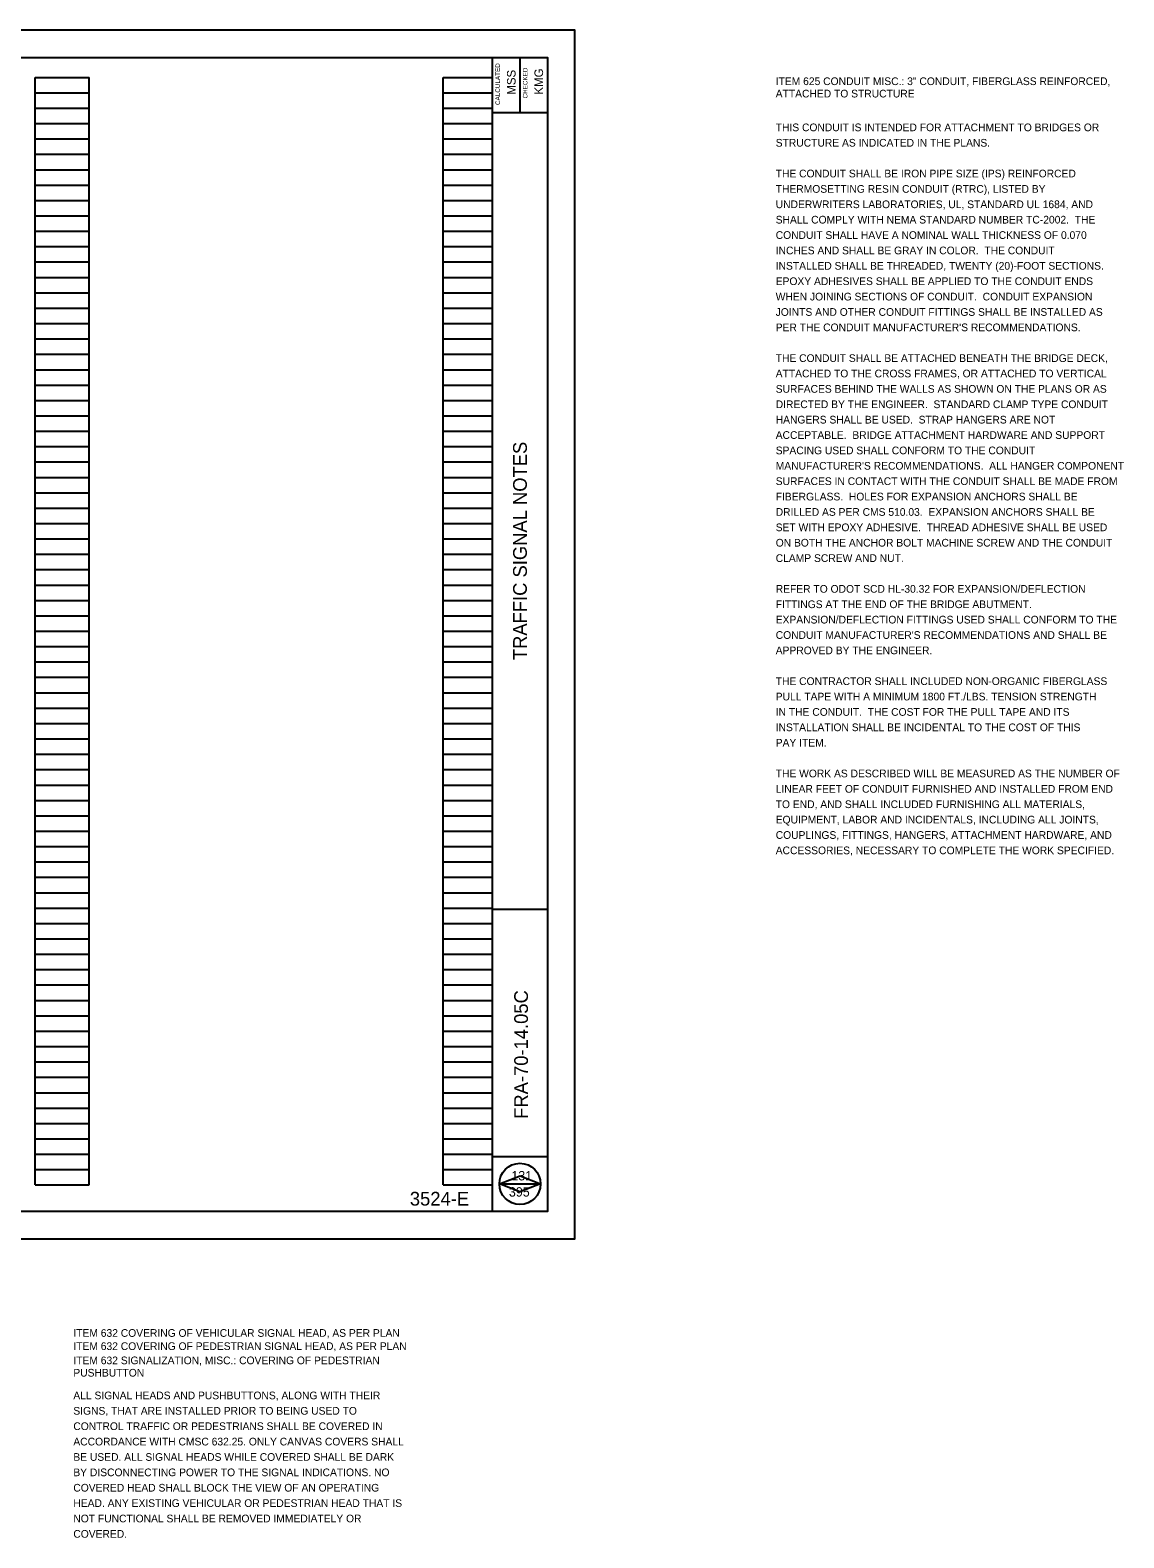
# Model space of a CAD drawing. Extents: x -50.5 to 43.5, y -13 to 19.8.
# Drawn here: x 23.58 to 43.48, y -12.95 to 14.49 of the extents above; entities that cross this region are included whole.
import ezdxf

# ---------------------------------------------------------------- set-up
doc = ezdxf.new("R2010")
doc.units = 0
for name, color, linetype in [('Level 63', 7, 'Continuous'), ('PF_P_Text', 7, 'Continuous'), ('SC_Scratch1', 7, 'Continuous'), ('SH_Cut_Line', 7, 'Continuous'), ('SH_Data', 7, 'Continuous'), ('SH_Text', 7, 'Continuous')]:
    doc.layers.add(name, color=color, linetype=linetype)

msp = doc.modelspace()

# ---------------------------------------------------------------- linework, layer by layer
at = {"layer": 'Level 63'}
msp.add_line((32.119, -6.508), (32.869, -6.508), dxfattribs=at)
msp.add_circle((32.494, -6.508), 0.375, dxfattribs=at)
at = {"layer": 'PF_P_Text'}
for p, q in [((31.994, -7.008), (31.994, 13.992)), ((32.494, 13.992), (32.494, 12.992)), ((31.994, 12.992), (32.994, 12.992)), ((31.994, -1.508), (32.994, -1.508)), ((31.994, -6.008), (32.994, -6.008))]:
    msp.add_line(p, q, dxfattribs=at)
msp.add_lwpolyline([(1.494, 13.992), (32.994, 13.992), (32.994, -7.008), (1.494, -7.008)], close=True, dxfattribs=at)
at = {"layer": 'SC_Scratch1'}
for p, q in [((23.674, -6.528), (23.674, 13.632)), ((23.674, 13.632), (24.654, 13.632)), ((24.654, -6.528), (24.654, 13.632)), ((31.094, -6.528), (31.094, 13.632)), ((31.094, 13.632), (31.994, 13.632)), ((31.994, -6.528), (31.994, 13.632)), ((23.674, 13.352), (24.654, 13.352)), ((31.094, 13.352), (31.994, 13.352)), ((23.674, 13.072), (24.654, 13.072)), ((31.094, 13.072), (31.994, 13.072)), ((23.674, 12.792), (24.654, 12.792)), ((31.094, 12.792), (31.994, 12.792)), ((23.674, 12.512), (24.654, 12.512)), ((31.094, 12.512), (31.994, 12.512)), ((23.674, 12.232), (24.654, 12.232)), ((31.094, 12.232), (31.994, 12.232)), ((23.674, 11.952), (24.654, 11.952)), ((31.094, 11.952), (31.994, 11.952)), ((23.674, 11.672), (24.654, 11.672)), ((31.094, 11.672), (31.994, 11.672)), ((23.674, 11.392), (24.654, 11.392)), ((31.094, 11.392), (31.994, 11.392)), ((23.674, 11.112), (24.654, 11.112)), ((31.094, 11.112), (31.994, 11.112)), ((23.674, 10.832), (24.654, 10.832)), ((31.094, 10.832), (31.994, 10.832)), ((23.674, 10.552), (24.654, 10.552)), ((31.094, 10.552), (31.994, 10.552)), ((23.674, 10.272), (24.654, 10.272)), ((31.094, 10.272), (31.994, 10.272)), ((23.674, 9.992), (24.654, 9.992)), ((31.094, 9.992), (31.994, 9.992)), ((23.674, 9.712), (24.654, 9.712)), ((31.094, 9.712), (31.994, 9.712)), ((23.674, 9.432), (24.654, 9.432)), ((31.094, 9.432), (31.994, 9.432)), ((23.674, 9.152), (24.654, 9.152)), ((31.094, 9.152), (31.994, 9.152)), ((23.674, 8.872), (24.654, 8.872)), ((31.094, 8.872), (31.994, 8.872)), ((23.674, 8.592), (24.654, 8.592)), ((31.094, 8.592), (31.994, 8.592)), ((23.674, 8.312), (24.654, 8.312)), ((31.094, 8.312), (31.994, 8.312)), ((23.674, 8.032), (24.654, 8.032)), ((31.094, 8.032), (31.994, 8.032)), ((23.674, 7.752), (24.654, 7.752)), ((31.094, 7.752), (31.994, 7.752)), ((23.674, 7.472), (24.654, 7.472)), ((31.094, 7.472), (31.994, 7.472)), ((23.674, 7.192), (24.654, 7.192)), ((31.094, 7.192), (31.994, 7.192)), ((23.674, 6.912), (24.654, 6.912)), ((31.094, 6.912), (31.994, 6.912)), ((23.674, 6.632), (24.654, 6.632)), ((31.094, 6.632), (31.994, 6.632)), ((23.674, 6.352), (24.654, 6.352)), ((31.094, 6.352), (31.994, 6.352)), ((23.674, 6.072), (24.654, 6.072)), ((31.094, 6.072), (31.994, 6.072)), ((23.674, 5.792), (24.654, 5.792)), ((31.094, 5.792), (31.994, 5.792)), ((23.674, 5.512), (24.654, 5.512)), ((31.094, 5.512), (31.994, 5.512)), ((23.674, 5.232), (24.654, 5.232)), ((31.094, 5.232), (31.994, 5.232)), ((23.674, 4.952), (24.654, 4.952)), ((31.094, 4.952), (31.994, 4.952)), ((23.674, 4.672), (24.654, 4.672)), ((31.094, 4.672), (31.994, 4.672)), ((23.674, 4.392), (24.654, 4.392)), ((31.094, 4.392), (31.994, 4.392)), ((23.674, 4.112), (24.654, 4.112)), ((31.094, 4.112), (31.994, 4.112)), ((23.674, 3.832), (24.654, 3.832)), ((31.094, 3.832), (31.994, 3.832)), ((23.674, 3.552), (24.654, 3.552)), ((31.094, 3.552), (31.994, 3.552)), ((23.674, 3.272), (24.654, 3.272)), ((31.094, 3.272), (31.994, 3.272)), ((23.674, 2.992), (24.654, 2.992)), ((31.094, 2.992), (31.994, 2.992)), ((23.674, 2.712), (24.654, 2.712)), ((31.094, 2.712), (31.994, 2.712)), ((23.674, 2.432), (24.654, 2.432)), ((31.094, 2.432), (31.994, 2.432)), ((23.674, 2.152), (24.654, 2.152)), ((31.094, 2.152), (31.994, 2.152)), ((23.674, 1.872), (24.654, 1.872)), ((31.094, 1.872), (31.994, 1.872)), ((23.674, 1.592), (24.654, 1.592)), ((31.094, 1.592), (31.994, 1.592)), ((23.674, 1.312), (24.654, 1.312)), ((31.094, 1.312), (31.994, 1.312)), ((23.674, 1.032), (24.654, 1.032)), ((31.094, 1.032), (31.994, 1.032)), ((23.674, 0.752), (24.654, 0.752)), ((31.094, 0.752), (31.994, 0.752)), ((23.674, 0.472), (24.654, 0.472)), ((31.094, 0.472), (31.994, 0.472)), ((23.674, 0.192), (24.654, 0.192)), ((31.094, 0.192), (31.994, 0.192)), ((23.674, -0.088), (24.654, -0.088)), ((31.094, -0.088), (31.994, -0.088)), ((23.674, -0.368), (24.654, -0.368)), ((31.094, -0.368), (31.994, -0.368)), ((23.674, -0.648), (24.654, -0.648)), ((31.094, -0.648), (31.994, -0.648)), ((23.674, -0.928), (24.654, -0.928)), ((31.094, -0.928), (31.994, -0.928)), ((23.674, -1.208), (24.654, -1.208)), ((31.094, -1.208), (31.994, -1.208)), ((23.674, -1.488), (24.654, -1.488)), ((31.094, -1.488), (31.994, -1.488)), ((23.674, -1.768), (24.654, -1.768)), ((31.094, -1.768), (31.994, -1.768)), ((23.674, -2.048), (24.654, -2.048)), ((31.094, -2.048), (31.994, -2.048)), ((23.674, -2.328), (24.654, -2.328)), ((31.094, -2.328), (31.994, -2.328)), ((23.674, -2.608), (24.654, -2.608)), ((31.094, -2.608), (31.994, -2.608)), ((23.674, -2.888), (24.654, -2.888)), ((31.094, -2.888), (31.994, -2.888)), ((23.674, -3.168), (24.654, -3.168)), ((31.094, -3.168), (31.994, -3.168)), ((23.674, -3.448), (24.654, -3.448)), ((31.094, -3.448), (31.994, -3.448)), ((23.674, -3.728), (24.654, -3.728)), ((31.094, -3.728), (31.994, -3.728)), ((23.674, -4.008), (24.654, -4.008)), ((31.094, -4.008), (31.994, -4.008)), ((23.674, -4.288), (24.654, -4.288)), ((31.094, -4.288), (31.994, -4.288)), ((23.674, -4.568), (24.654, -4.568)), ((31.094, -4.568), (31.994, -4.568)), ((23.674, -4.848), (24.654, -4.848)), ((31.094, -4.848), (31.994, -4.848)), ((23.674, -5.128), (24.654, -5.128)), ((31.094, -5.128), (31.994, -5.128)), ((23.674, -5.408), (24.654, -5.408)), ((31.094, -5.408), (31.994, -5.408)), ((23.674, -5.688), (24.654, -5.688)), ((31.094, -5.688), (31.994, -5.688)), ((23.674, -5.968), (24.654, -5.968)), ((31.094, -5.968), (31.994, -5.968)), ((23.674, -6.248), (24.654, -6.248)), ((31.094, -6.248), (31.994, -6.248)), ((23.674, -6.528), (24.654, -6.528)), ((31.094, -6.528), (31.994, -6.528)), ((32.119, -6.508), (32.495, -6.36)), ((32.49, -6.654), (32.119, -6.508)), ((32.869, -6.508), (32.49, -6.654)), ((32.495, -6.36), (32.869, -6.508))]:
    msp.add_line(p, q, dxfattribs=at)
at = {"layer": 'SH_Cut_Line'}
msp.add_lwpolyline([(-0.506, -7.508), (33.494, -7.508), (33.494, 14.492), (-0.506, 14.492)], close=True, dxfattribs=at)

# ---------------------------------------------------------------- texts
at = {"layer": 'Level 63'}
for s, p in [('CALCULATED', (32.13, 13.129)), ('CHECKED', (32.63, 13.248))]:
    msp.add_text(s, height=0.0833, rotation=90, dxfattribs=at).set_placement(p)
at = {"layer": 'SH_Data'}
for s, p in [('ITEM 625 CONDUIT MISC.: 3" CONDUIT, FIBERGLASS REINFORCED, ', (37.147, 13.492)), ('ATTACHED TO STRUCTURE', (37.147, 13.267)), ('ITEM 632 COVERING OF VEHICULAR SIGNAL HEAD, AS PER PLAN', (24.367, -9.292)), ('ITEM 632 COVERING OF PEDESTRIAN SIGNAL HEAD, AS PER PLAN', (24.367, -9.532)), ('PUSHBUTTON', (24.367, -10.016)), ('ITEM 632 SIGNALIZATION, MISC.: COVERING OF PEDESTRIAN ', (24.367, -9.791)), ('ALL SIGNAL HEADS AND PUSHBUTTONS, ALONG WITH THEIR ', (24.367, -10.429)), ('SIGNS, THAT ARE INSTALLED PRIOR TO BEING USED TO ', (24.367, -10.709)), ('CONTROL TRAFFIC OR PEDESTRIANS SHALL BE COVERED IN ', (24.367, -10.989)), ('ACCORDANCE WITH CMSC 632.25. ONLY CANVAS COVERS SHALL ', (24.367, -11.269)), ('BE USED. ALL SIGNAL HEADS WHILE COVERED SHALL BE DARK ', (24.367, -11.549)), ('BY DISCONNECTING POWER TO THE SIGNAL INDICATIONS. NO ', (24.367, -11.829)), ('COVERED HEAD SHALL BLOCK THE VIEW OF AN OPERATING ', (24.367, -12.109)), ('HEAD. ANY EXISTING VEHICULAR OR PEDESTRIAN HEAD THAT IS ', (24.367, -12.389)), ('NOT FUNCTIONAL SHALL BE REMOVED IMMEDIATELY OR ', (24.367, -12.669)), ('COVERED. ', (24.367, -12.949))]:
    msp.add_text(s, height=0.14, dxfattribs=at).set_placement(p)
at = {"layer": 'SH_Text'}
for s, height, rotation, p in [('MSS', 0.156, 90, (32.414, 13.317)), ('KMG', 0.156, 90, (32.914, 13.319)), ('TRAFFIC SIGNAL NOTES', 0.25, 90, (32.619, 3.025)), ('FRA-70-14.05C', 0.25, 90, (32.639, -5.324)), ('3524-E', 0.25, 359.9999, (30.49, -6.903))]:
    msp.add_text(s, height=height, rotation=rotation, dxfattribs=at).set_placement(p)
for s, height, p in [('THIS CONDUIT IS INTENDED FOR ATTACHMENT TO BRIDGES OR ', 0.14, (37.147, 12.652)), ('STRUCTURE AS INDICATED IN THE PLANS.', 0.14, (37.147, 12.372)), ('THE CONDUIT SHALL BE IRON PIPE SIZE (IPS) REINFORCED ', 0.14, (37.147, 11.812)), ('THERMOSETTING RESIN CONDUIT (RTRC), LISTED BY ', 0.14, (37.147, 11.532)), ('UNDERWRITERS LABORATORIES, UL, STANDARD UL 1684, AND ', 0.14, (37.147, 11.252)), ('SHALL COMPLY WITH NEMA STANDARD NUMBER TC-2002.  THE ', 0.14, (37.147, 10.972)), ('CONDUIT SHALL HAVE A NOMINAL WALL THICKNESS OF 0.070 ', 0.14, (37.147, 10.692)), ('INCHES AND SHALL BE GRAY IN COLOR.  THE CONDUIT ', 0.14, (37.147, 10.412)), ('INSTALLED SHALL BE THREADED, TWENTY (20)-FOOT SECTIONS.  ', 0.14, (37.147, 10.132)), ('EPOXY ADHESIVES SHALL BE APPLIED TO THE CONDUIT ENDS ', 0.14, (37.147, 9.852)), ('WHEN JOINING SECTIONS OF CONDUIT.  CONDUIT EXPANSION ', 0.14, (37.147, 9.572)), ('JOINTS AND OTHER CONDUIT FITTINGS SHALL BE INSTALLED AS ', 0.14, (37.147, 9.292)), ("PER THE CONDUIT MANUFACTURER'S RECOMMENDATIONS.", 0.14, (37.147, 9.012)), ('THE CONDUIT SHALL BE ATTACHED BENEATH THE BRIDGE DECK, ', 0.14, (37.147, 8.452)), ('ATTACHED TO THE CROSS FRAMES, OR ATTACHED TO VERTICAL ', 0.14, (37.147, 8.172)), ('SURFACES BEHIND THE WALLS AS SHOWN ON THE PLANS OR AS ', 0.14, (37.147, 7.892)), ('DIRECTED BY THE ENGINEER.  STANDARD CLAMP TYPE CONDUIT ', 0.14, (37.147, 7.612)), ('HANGERS SHALL BE USED.  STRAP HANGERS ARE NOT ', 0.14, (37.147, 7.332)), ('ACCEPTABLE.  BRIDGE ATTACHMENT HARDWARE AND SUPPORT ', 0.14, (37.147, 7.052)), ('SPACING USED SHALL CONFORM TO THE CONDUIT ', 0.14, (37.147, 6.772)), ("MANUFACTURER'S RECOMMENDATIONS.  ALL HANGER COMPONENT ", 0.14, (37.147, 6.492)), ('SURFACES IN CONTACT WITH THE CONDUIT SHALL BE MADE FROM ', 0.14, (37.147, 6.212)), ('FIBERGLASS.  HOLES FOR EXPANSION ANCHORS SHALL BE ', 0.14, (37.147, 5.932)), ('DRILLED AS PER CMS 510.03.  EXPANSION ANCHORS SHALL BE ', 0.14, (37.147, 5.652)), ('SET WITH EPOXY ADHESIVE.  THREAD ADHESIVE SHALL BE USED ', 0.14, (37.147, 5.372)), ('ON BOTH THE ANCHOR BOLT MACHINE SCREW AND THE CONDUIT ', 0.14, (37.147, 5.092)), ('CLAMP SCREW AND NUT.', 0.14, (37.147, 4.812)), ('REFER TO ODOT SCD HL-30.32 FOR EXPANSION/DEFLECTION ', 0.14, (37.147, 4.252)), ('FITTINGS AT THE END OF THE BRIDGE ABUTMENT.  ', 0.14, (37.147, 3.972)), ('EXPANSION/DEFLECTION FITTINGS USED SHALL CONFORM TO THE ', 0.14, (37.147, 3.692)), ("CONDUIT MANUFACTURER'S RECOMMENDATIONS AND SHALL BE ", 0.14, (37.147, 3.412)), ('APPROVED BY THE ENGINEER.', 0.14, (37.147, 3.132)), ('THE CONTRACTOR SHALL INCLUDED NON-ORGANIC FIBERGLASS ', 0.14, (37.147, 2.572)), ('PULL TAPE WITH A MINIMUM 1800 FT./LBS. TENSION STRENGTH ', 0.14, (37.147, 2.292)), ('IN THE CONDUIT.  THE COST FOR THE PULL TAPE AND ITS ', 0.14, (37.147, 2.012)), ('INSTALLATION SHALL BE INCIDENTAL TO THE COST OF THIS ', 0.14, (37.147, 1.732)), ('PAY ITEM.', 0.14, (37.147, 1.452)), ('THE WORK AS DESCRIBED WILL BE MEASURED AS THE NUMBER OF ', 0.14, (37.147, 0.892)), ('LINEAR FEET OF CONDUIT FURNISHED AND INSTALLED FROM END ', 0.14, (37.147, 0.612)), ('TO END, AND SHALL INCLUDED FURNISHING ALL MATERIALS, ', 0.14, (37.147, 0.332)), ('EQUIPMENT, LABOR AND INCIDENTALS, INCLUDING ALL JOINTS, ', 0.14, (37.147, 0.052)), ('COUPLINGS, FITTINGS, HANGERS, ATTACHMENT HARDWARE, AND ', 0.14, (37.147, -0.228)), ('ACCESSORIES, NECESSARY TO COMPLETE THE WORK SPECIFIED.', 0.14, (37.147, -0.508)), ('131', 0.17, (32.336, -6.445)), ('395', 0.17, (32.292, -6.739))]:
    msp.add_text(s, height=height, dxfattribs=at).set_placement(p)

doc.saveas('drawing.dxf')
